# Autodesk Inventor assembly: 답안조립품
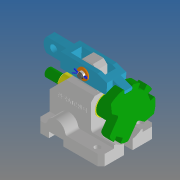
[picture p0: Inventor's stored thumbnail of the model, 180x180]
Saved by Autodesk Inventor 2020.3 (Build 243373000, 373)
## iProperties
Created: 2022-08
Part Number: 답안조립품
Document SubType Name: Assembly
Designer: EZDESIGN
Author: EZDESIGN
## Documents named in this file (8)
- Y:\720806V1002\답안조립품.iam
- Y:\720806V1002\720806V1002\부시.ipt
- Y:\720806V1002\720806V1002\분할대.ipt
- Y:\720806V1002\720806V1002\분할축.ipt
- Y:\720806V1002\720806V1002\분할핀.ipt
- Y:\720806V1002\720806V1002\와셔.ipt
- Y:\720806V1002\720806V1002\클레비스핀.ipt
- Y:\720806V1002\본체.ipt
